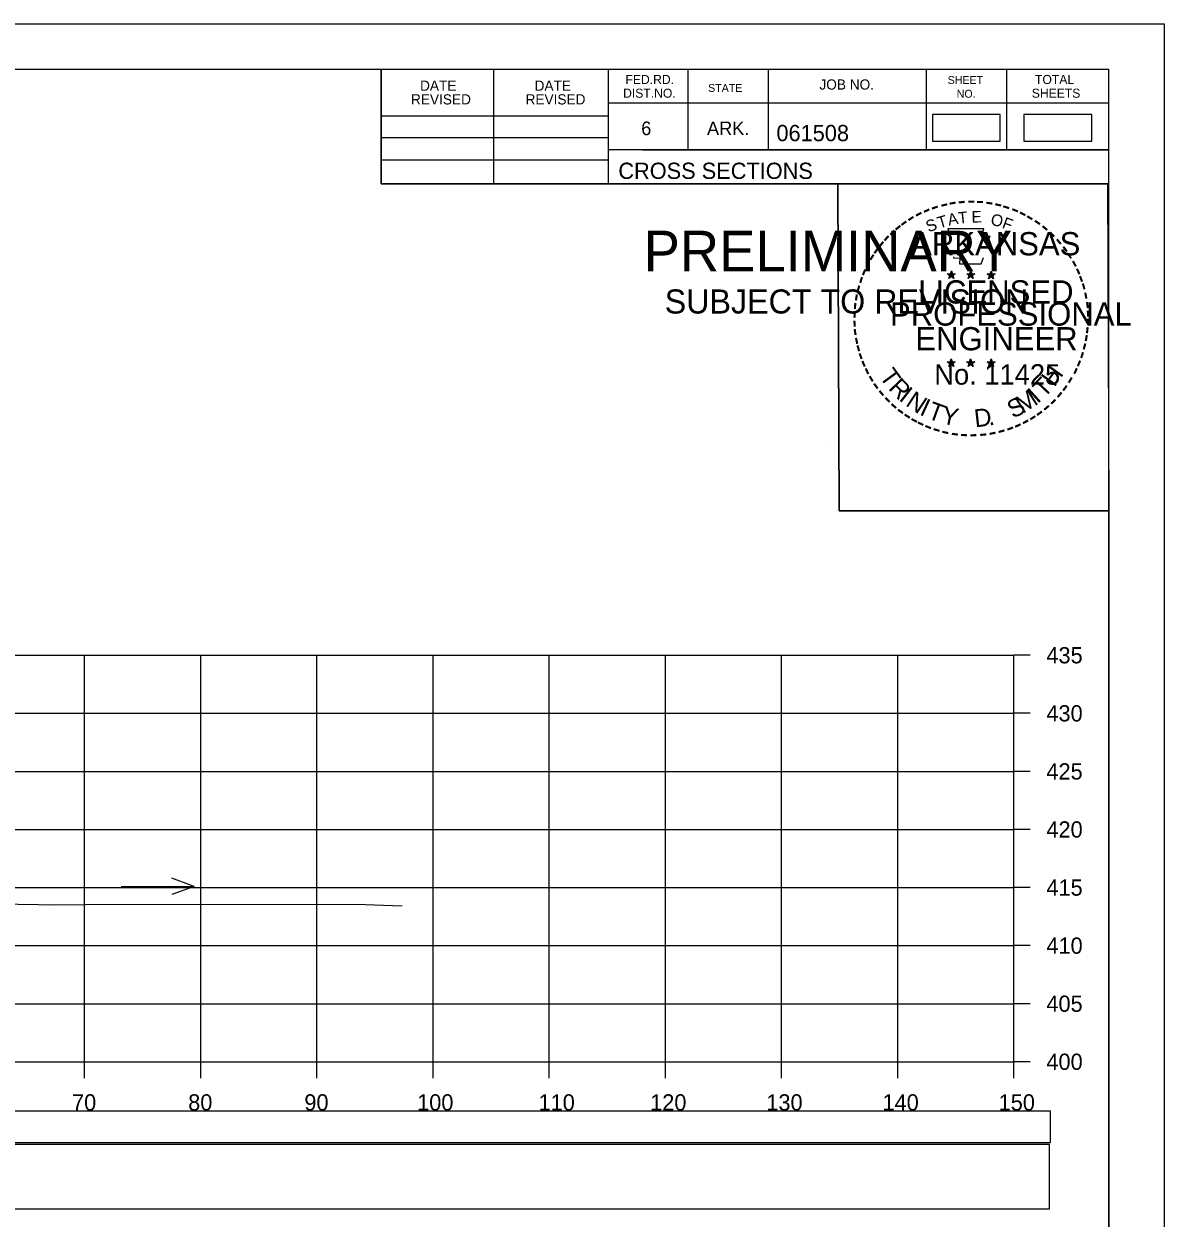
# Model space of a CAD drawing. Extents: x 1371057 to 1372761, y 380005 to 390517.
# Drawn here: x 1371625.6 to 1371723.8, y 386089.1 to 386191.9 of the extents above; entities that cross this region are included whole.
import ezdxf

# ---------------------------------------------------------------- set-up
doc = ezdxf.new("R2010")
doc.units = 0
for name, color, linetype in [('R_Axis', 7, 'Continuous'), ('R_Axis Annot', 7, 'Continuous'), ('R_Border', 7, 'Continuous'), ('R_Border PE', 7, 'Continuous'), ('R_Border Prem', 7, 'Continuous'), ('R_Detour', 7, 'Continuous'), ('R_Dimension', 7, 'Continuous'), ('R_Draft', 7, 'Continuous'), ('R_Exist Surface', 7, 'Continuous'), ('R_Grid', 7, 'Continuous'), ('R_No Plot', 7, 'Continuous'), ('R_Water Annot', 7, 'Continuous')]:
    doc.layers.add(name, color=color, linetype=linetype)

msp = doc.modelspace()

# ---------------------------------------------------------------- linework, layer by layer
at = {"layer": 'R_Axis'}
for p, q in [((1371710.87, 386102.52), (1371710.87, 386137.52)), ((1371712.27, 386137.52), (1371710.87, 386137.52)), ((1371712.27, 386132.52), (1371710.87, 386132.52)), ((1371712.27, 386127.52), (1371710.87, 386127.52)), ((1371712.27, 386122.52), (1371710.87, 386122.52)), ((1371712.27, 386117.52), (1371710.87, 386117.52)), ((1371712.27, 386112.52), (1371710.87, 386112.52)), ((1371712.27, 386107.52), (1371710.87, 386107.52)), ((1371410.87, 386102.52), (1371710.87, 386102.52)), ((1371630.87, 386101.12), (1371630.87, 386102.52)), ((1371640.87, 386101.12), (1371640.87, 386102.52)), ((1371650.87, 386101.12), (1371650.87, 386102.52)), ((1371660.87, 386101.12), (1371660.87, 386102.52)), ((1371670.87, 386101.12), (1371670.87, 386102.52)), ((1371680.87, 386101.12), (1371680.87, 386102.52)), ((1371690.87, 386101.12), (1371690.87, 386102.52)), ((1371700.87, 386101.12), (1371700.87, 386102.52)), ((1371710.87, 386101.12), (1371710.87, 386102.52)), ((1371712.27, 386102.52), (1371710.87, 386102.52))]:
    msp.add_line(p, q, dxfattribs=at)
at = {"layer": 'R_Border'}
for p, q in [((1371402.87, 386187.98), (1371719.05, 386187.98)), ((1371656.41, 386178.1), (1371656.41, 386187.98)), ((1371666.09, 386178.1), (1371666.09, 386187.98)), ((1371675.95, 386187.98), (1371675.95, 386178.1)), ((1371682.79, 386187.98), (1371682.79, 386181.04)), ((1371689.73, 386187.98), (1371689.73, 386181.04)), ((1371703.31, 386187.98), (1371703.31, 386181.04)), ((1371710.25, 386187.98), (1371710.25, 386181.04)), ((1371719.05, 385982.52), (1371719.05, 386187.98)), ((1371719.05, 386185.04), (1371675.95, 386185.04)), ((1371719.05, 386185.06), (1371719.05, 386185.06)), ((1371656.41, 386183.96), (1371675.95, 386183.96)), ((1371656.41, 386182.1), (1371675.95, 386182.1)), ((1371719.05, 386181.04), (1371675.95, 386181.04)), ((1371678.91, 386181.04), (1371719.05, 386181.04)), ((1371656.41, 386180.16), (1371675.95, 386180.16)), ((1371719.05, 386178.1), (1371656.41, 386178.1))]:
    msp.add_line(p, q, dxfattribs=at)
at = {"layer": 'R_Border PE'}
for p, q in [((1371705.14, 386170.36), (1371705.49, 386170.25)), ((1371705.14, 386170.36), (1371705.39, 386170.31)), ((1371705.14, 386170.36), (1371705.37, 386170.24)), ((1371705.49, 386170.61), (1371705.45, 386170.36)), ((1371705.49, 386170.25), (1371705.49, 386170.61)), ((1371705.49, 386170.61), (1371705.54, 386170.36)), ((1371705.83, 386170.36), (1371705.49, 386170.25)), ((1371705.83, 386170.36), (1371705.55, 386170.31)), ((1371705.83, 386170.36), (1371705.63, 386170.26)), ((1371706.81, 386170.36), (1371707.16, 386170.25)), ((1371706.81, 386170.36), (1371707.06, 386170.31)), ((1371706.81, 386170.36), (1371707.04, 386170.24)), ((1371707.16, 386170.61), (1371707.12, 386170.36)), ((1371707.16, 386170.25), (1371707.16, 386170.61)), ((1371707.16, 386170.61), (1371707.21, 386170.36)), ((1371707.5, 386170.36), (1371707.16, 386170.25)), ((1371707.5, 386170.36), (1371707.22, 386170.31)), ((1371707.5, 386170.36), (1371707.3, 386170.26)), ((1371708.57, 386170.35), (1371708.92, 386170.24)), ((1371708.57, 386170.35), (1371708.82, 386170.3)), ((1371708.57, 386170.35), (1371708.81, 386170.22)), ((1371708.92, 386170.6), (1371708.88, 386170.35)), ((1371708.92, 386170.24), (1371708.92, 386170.6)), ((1371708.92, 386170.6), (1371708.97, 386170.35)), ((1371709.27, 386170.35), (1371708.92, 386170.24)), ((1371709.27, 386170.35), (1371708.98, 386170.3)), ((1371709.27, 386170.35), (1371709.06, 386170.24)), ((1371705.27, 386169.95), (1371705.49, 386170.25)), ((1371705.27, 386169.95), (1371705.4, 386170.19)), ((1371705.27, 386169.95), (1371705.48, 386170.17)), ((1371705.7, 386169.95), (1371705.48, 386170.16)), ((1371705.7, 386169.95), (1371705.49, 386170.25)), ((1371705.7, 386169.95), (1371705.56, 386170.24)), ((1371706.94, 386169.95), (1371707.16, 386170.25)), ((1371706.94, 386169.95), (1371707.07, 386170.19)), ((1371706.94, 386169.95), (1371707.15, 386170.17)), ((1371707.37, 386169.95), (1371707.15, 386170.16)), ((1371707.37, 386169.95), (1371707.16, 386170.25)), ((1371707.37, 386169.95), (1371707.23, 386170.24)), ((1371708.7, 386169.94), (1371708.92, 386170.24)), ((1371708.7, 386169.94), (1371708.83, 386170.18)), ((1371708.7, 386169.94), (1371708.92, 386170.16)), ((1371709.13, 386169.94), (1371708.92, 386170.24)), ((1371709.13, 386169.94), (1371708.92, 386170.15)), ((1371709.13, 386169.94), (1371709, 386170.23)), ((1371705.13, 386162.79), (1371705.48, 386162.67)), ((1371705.13, 386162.79), (1371705.39, 386162.74)), ((1371705.13, 386162.79), (1371705.37, 386162.66)), ((1371705.27, 386162.38), (1371705.48, 386162.67)), ((1371705.27, 386162.38), (1371705.39, 386162.62)), ((1371705.27, 386162.38), (1371705.48, 386162.59)), ((1371705.48, 386163.04), (1371705.44, 386162.79)), ((1371705.48, 386162.67), (1371705.48, 386163.04)), ((1371705.48, 386163.04), (1371705.53, 386162.79)), ((1371705.83, 386162.79), (1371705.48, 386162.67)), ((1371705.7, 386162.38), (1371705.48, 386162.67)), ((1371705.7, 386162.38), (1371705.48, 386162.59)), ((1371705.83, 386162.79), (1371705.54, 386162.74)), ((1371705.7, 386162.38), (1371705.56, 386162.67)), ((1371705.83, 386162.79), (1371705.63, 386162.68)), ((1371706.8, 386162.79), (1371707.15, 386162.67)), ((1371706.8, 386162.79), (1371707.06, 386162.74)), ((1371706.8, 386162.79), (1371707.04, 386162.66)), ((1371706.94, 386162.38), (1371707.15, 386162.67)), ((1371706.94, 386162.38), (1371707.06, 386162.62)), ((1371706.94, 386162.38), (1371707.15, 386162.59)), ((1371707.15, 386163.04), (1371707.11, 386162.79)), ((1371707.15, 386162.67), (1371707.15, 386163.04)), ((1371707.15, 386163.04), (1371707.2, 386162.79)), ((1371707.5, 386162.79), (1371707.15, 386162.67)), ((1371707.36, 386162.38), (1371707.15, 386162.67)), ((1371707.36, 386162.38), (1371707.15, 386162.59)), ((1371707.5, 386162.79), (1371707.21, 386162.74)), ((1371707.36, 386162.38), (1371707.23, 386162.67)), ((1371707.5, 386162.79), (1371707.29, 386162.68)), ((1371708.57, 386162.78), (1371708.92, 386162.66)), ((1371708.57, 386162.78), (1371708.82, 386162.73)), ((1371708.57, 386162.78), (1371708.81, 386162.65)), ((1371708.7, 386162.37), (1371708.92, 386162.66)), ((1371708.7, 386162.37), (1371708.83, 386162.61)), ((1371708.7, 386162.37), (1371708.92, 386162.58)), ((1371708.92, 386163.03), (1371708.88, 386162.78)), ((1371708.92, 386162.66), (1371708.92, 386163.03)), ((1371708.92, 386163.03), (1371708.97, 386162.78)), ((1371709.27, 386162.78), (1371708.92, 386162.66)), ((1371709.13, 386162.37), (1371708.92, 386162.66)), ((1371709.13, 386162.37), (1371708.92, 386162.58)), ((1371709.27, 386162.78), (1371708.98, 386162.73)), ((1371709.13, 386162.37), (1371708.99, 386162.66)), ((1371709.27, 386162.78), (1371709.06, 386162.67))]:
    msp.add_line(p, q, dxfattribs=at)
for points in [[(1371705.18, 386174.24), (1371705.45, 386173.41)], [(1371708.69, 386173.31), (1371708.83, 386173.6), (1371708.15, 386173.57), (1371708.29, 386174.24), (1371705.18, 386174.24)], [(1371705.67, 386171.81), (1371705.67, 386171.73), (1371706.23, 386171.71), (1371706.18, 386171.23), (1371708.05, 386171.23), (1371708.25, 386171.77)], [(1371705.49, 386170.61), (1371705.7, 386169.95), (1371705.14, 386170.36), (1371705.83, 386170.36), (1371705.27, 386169.95), (1371705.49, 386170.61)], [(1371707.16, 386170.61), (1371707.37, 386169.95), (1371706.81, 386170.36), (1371707.5, 386170.36), (1371706.94, 386169.95), (1371707.16, 386170.61)], [(1371708.92, 386170.6), (1371709.13, 386169.94), (1371708.57, 386170.35), (1371709.27, 386170.35), (1371708.7, 386169.94), (1371708.92, 386170.6)], [(1371705.48, 386163.04), (1371705.7, 386162.38), (1371705.13, 386162.79), (1371705.83, 386162.79), (1371705.27, 386162.38), (1371705.48, 386163.04)], [(1371707.15, 386163.04), (1371707.36, 386162.38), (1371706.8, 386162.79), (1371707.5, 386162.79), (1371706.94, 386162.38), (1371707.15, 386163.04)], [(1371708.92, 386163.03), (1371709.13, 386162.37), (1371708.57, 386162.78), (1371709.27, 386162.78), (1371708.7, 386162.37), (1371708.92, 386163.03)]]:
    msp.add_lwpolyline(points, dxfattribs=at)
for centre, radius in [((1371705.49, 386170.25), 0.172), ((1371705.49, 386170.25), 0.145), ((1371705.49, 386170.25), 0.116), ((1371705.49, 386170.25), 0.0991), ((1371705.49, 386170.25), 0.0747), ((1371707.16, 386170.25), 0.172), ((1371707.16, 386170.25), 0.145), ((1371707.16, 386170.25), 0.116), ((1371707.16, 386170.25), 0.0991), ((1371707.16, 386170.25), 0.0747), ((1371708.92, 386170.23), 0.172), ((1371708.92, 386170.23), 0.145), ((1371708.92, 386170.23), 0.116), ((1371708.92, 386170.23), 0.0991), ((1371705.49, 386170.25), 0.0495), ((1371705.49, 386170.25), 0.0296), ((1371707.16, 386170.25), 0.0495), ((1371707.16, 386170.25), 0.0296), ((1371708.92, 386170.23), 0.0747), ((1371708.92, 386170.23), 0.0495), ((1371708.92, 386170.23), 0.0296), ((1371705.48, 386162.67), 0.172), ((1371705.48, 386162.67), 0.145), ((1371705.48, 386162.67), 0.116), ((1371705.48, 386162.67), 0.0991), ((1371705.48, 386162.67), 0.0747), ((1371705.48, 386162.67), 0.0495), ((1371705.48, 386162.67), 0.0296), ((1371707.15, 386162.67), 0.172), ((1371707.15, 386162.67), 0.145), ((1371707.15, 386162.67), 0.116), ((1371707.15, 386162.67), 0.0991), ((1371707.15, 386162.67), 0.0747), ((1371707.15, 386162.67), 0.0495), ((1371707.15, 386162.67), 0.0296), ((1371708.92, 386162.66), 0.172), ((1371708.92, 386162.66), 0.145), ((1371708.92, 386162.66), 0.116), ((1371708.92, 386162.66), 0.0991), ((1371708.92, 386162.66), 0.0747), ((1371708.92, 386162.66), 0.0495), ((1371708.92, 386162.66), 0.0296)]:
    msp.add_circle(centre, radius, dxfattribs=at)
at = {"layer": 'R_Detour'}
msp.add_lwpolyline([(1371407.72, 386095.57), (1371714.03, 386095.57), (1371714.03, 386098.28), (1371407.72, 386098.28)], close=True, dxfattribs=at)
at = {"layer": 'R_Dimension'}
for points in [[(1371703.87, 386181.77), (1371709.7, 386181.77), (1371709.7, 386184.08), (1371703.87, 386184.08)], [(1371711.74, 386181.77), (1371717.57, 386181.77), (1371717.57, 386184.08), (1371711.74, 386184.08)]]:
    msp.add_lwpolyline(points, close=True, dxfattribs=at)
at = {"layer": 'R_Draft'}
msp.add_lwpolyline([(1371407.64, 386089.87), (1371713.95, 386089.87), (1371713.95, 386095.4), (1371407.64, 386095.4)], close=True, dxfattribs=at)
at = {"layer": 'R_Exist Surface'}
msp.add_lwpolyline([(1371609.43, 386116.34), (1371626.89, 386116.05), (1371627.85, 386116.04), (1371630.95, 386116.05), (1371651.05, 386116.1), (1371655.04, 386116.07), (1371657.37, 386115.98), (1371658.2, 386115.95)], dxfattribs=at)
at = {"layer": 'R_Grid'}
for p, q in [((1371410.87, 386137.52), (1371710.87, 386137.52)), ((1371630.87, 386102.52), (1371630.87, 386137.52)), ((1371640.87, 386102.52), (1371640.87, 386137.52)), ((1371650.87, 386102.52), (1371650.87, 386137.52)), ((1371660.87, 386102.52), (1371660.87, 386137.52)), ((1371670.87, 386102.52), (1371670.87, 386137.52)), ((1371680.87, 386102.52), (1371680.87, 386137.52)), ((1371690.87, 386102.52), (1371690.87, 386137.52)), ((1371700.87, 386102.52), (1371700.87, 386137.52)), ((1371710.87, 386102.52), (1371710.87, 386137.52)), ((1371410.87, 386132.52), (1371710.87, 386132.52)), ((1371410.87, 386127.52), (1371710.87, 386127.52)), ((1371410.87, 386122.52), (1371710.87, 386122.52)), ((1371410.87, 386117.52), (1371710.87, 386117.52)), ((1371410.87, 386112.52), (1371710.87, 386112.52)), ((1371410.87, 386107.52), (1371710.87, 386107.52)), ((1371410.87, 386102.52), (1371710.87, 386102.52))]:
    msp.add_line(p, q, dxfattribs=at)
at = {"layer": 'R_No Plot'}
for p, q in [((1371390.47, 386191.88), (1371723.8, 386191.88)), ((1371695.09, 386155.65), (1371695.09, 386155.65))]:
    msp.add_line(p, q, dxfattribs=at)
for points in [[(1371390.46, 386191.88), (1371723.8, 386191.88), (1371723.8, 385978.54), (1371390.46, 385978.54)], [(1371636.79, 386187.98), (1371656.41, 386187.98), (1371656.41, 386178.1), (1371672.52, 386178.1), (1371695.72, 386178.1), (1371695.84, 386149.95), (1371719.05, 386149.95), (1371719.05, 385982.52), (1371402.87, 385982.52), (1371402.87, 386187.98)], [(1371695.72, 386178.1), (1371718.93, 386178.1), (1371719.05, 386149.95), (1371695.84, 386149.95)]]:
    msp.add_lwpolyline(points, close=True, dxfattribs=at)
at = {"layer": 'R_Water Annot'}
for p, q in [((1371640.3, 386117.62), (1371638.38, 386118.32)), ((1371634.02, 386117.62), (1371640.3, 386117.62)), ((1371640.3, 386117.62), (1371638.38, 386116.92))]:
    msp.add_line(p, q, dxfattribs=at)

# ---------------------------------------------------------------- texts
at = {"layer": 'R_Axis Annot'}
for s, p in [('435', (1371713.67, 386136.82)), ('430', (1371713.67, 386131.82)), ('425', (1371713.67, 386126.82)), ('420', (1371713.67, 386121.82)), ('415', (1371713.67, 386116.82)), ('410', (1371713.67, 386111.82)), ('405', (1371713.67, 386106.82)), ('400', (1371713.67, 386101.82)), ('70', (1371629.79, 386098.32)), ('80', (1371639.79, 386098.32)), ('90', (1371649.79, 386098.32)), ('100', (1371659.5, 386098.32)), ('110', (1371669.95, 386098.32)), ('120', (1371679.56, 386098.32)), ('130', (1371689.56, 386098.32)), ('140', (1371699.56, 386098.32)), ('150', (1371709.56, 386098.32))]:
    msp.add_text(s, height=1.4, dxfattribs=at).set_placement(p)
at = {"layer": 'R_Border'}
for s, height, p in [('DATE', 0.879, (1371659.75, 386186.12)), ('DATE', 0.879, (1371669.61, 386186.12)), ('FED.RD.', 0.782, (1371677.43, 386186.7)), ('JOB NO.', 0.879, (1371694.13, 386186.22)), ('SHEET', 0.684, (1371705.17, 386186.7)), ('TOTAL', 0.782, (1371712.69, 386186.7)), ('REVISED', 0.879, (1371658.97, 386184.94)), ('REVISED', 0.879, (1371668.83, 386184.94)), ('DIST.NO.', 0.782, (1371677.23, 386185.52)), ('STATE', 0.684, (1371684.55, 386186.02)), ('NO.', 0.684, (1371705.95, 386185.52)), ('SHEETS', 0.782, (1371712.41, 386185.52)), ('6', 1.17, (1371678.79, 386182.3)), ('ARK.', 1.172, (1371684.45, 386182.3)), ('061508', 1.4, (1371690.43, 386181.78)), ('CROSS SECTIONS', 1.4, (1371676.82, 386178.53))]:
    msp.add_text(s, height=height, rotation=360, dxfattribs=at).set_placement(p)
at = {"layer": 'R_Border PE'}
for s, height, rotation, p in [('-', 1.6, 10.2193, (1371705.35, 386175.77)), ('-', 1.6, 5.8968, (1371706.08, 386175.88)), ('-', 1.6, 0.1862, (1371706.86, 386175.95)), ('-', 1.6, 357.743, (1371707.58, 386175.94)), ('-', 1.6, 352.1617, (1371708.32, 386175.88)), ('-', 1.6, 28.7918, (1371702.66, 386174.78)), ('-', 1.6, 24.3072, (1371703.29, 386175.09)), ('-', 1.6, 19.1761, (1371703.93, 386175.36)), ('-', 1.6, 13.6301, (1371704.68, 386175.6)), ('A', 1, 11.2132, (1371705.27, 386174.5)), ('T', 1, 6.0228, (1371706.12, 386174.66)), ('E', 1, 0.8323, (1371707.23, 386174.77)), ('O', 1, 350.4515, (1371708.83, 386174.56)), ('-', 1.6, 347.2049, (1371709.04, 386175.77)), ('-', 1.6, 342.3362, (1371709.68, 386175.61)), ('-', 1.6, 337.8551, (1371710.41, 386175.39)), ('-', 1.6, 334.1211, (1371711.04, 386175.12)), ('-', 1.6, 38.9507, (1371701.01, 386173.63)), ('-', 1.6, 36.2317, (1371701.48, 386174.01)), ('-', 1.6, 34.0636, (1371702.06, 386174.41)), ('S', 1, 21.594, (1371703.53, 386173.91)), ('T', 1, 16.4036, (1371704.45, 386174.25)), ('F', 1, 340.0707, (1371709.79, 386174.33)), ('-', 1.6, 329.6409, (1371711.62, 386174.83)), ('-', 1.6, 325.8627, (1371712.26, 386174.47)), ('-', 1.6, 320.5297, (1371712.87, 386174.05)), ('-', 1.6, 48.423, (1371700.13, 386172.74)), ('-', 1.6, 42.9622, (1371700.58, 386173.22)), ('ARKANSAS', 2, 360, (1371702.03, 386171.95)), ('-', 1.6, 315.5786, (1371713.47, 386173.56)), ('-', 1.6, 54.2325, (1371699.31, 386171.69)), ('-', 1.6, 50.6142, (1371699.72, 386172.25)), ('-', 1.6, 309.8797, (1371714.04, 386173.01)), ('-', 1.6, 306.6522, (1371714.57, 386172.41)), ('-', 1.6, 62.8713, (1371698.67, 386170.55)), ('-', 1.6, 58.0706, (1371698.99, 386171.16)), ('-', 1.4, 303.6753, (1371715.05, 386171.84)), ('-', 1.6, 299.6684, (1371715.37, 386171.23)), ('-', 1.6, 67.7743, (1371698.41, 386169.93)), ('-', 1.6, 294.6628, (1371715.7, 386170.62)), ('-', 1.6, 75.461, (1371698, 386168.59)), ('-', 1.6, 72.3945, (1371698.2, 386169.3)), ('LICENSED', 2, 360, (1371702.63, 386167.8)), ('DWB', 0.01, 360, (1371705.47, 386170.24)), ('DWB', 0.01, 360, (1371707.14, 386170.24)), ('DWB', 0.01, 360, (1371708.91, 386170.23)), ('-', 1.6, 290.5728, (1371715.95, 386170.04)), ('-', 1.6, 285.1233, (1371716.19, 386169.46)), ('-', 1.6, 81.2013, (1371697.87, 386167.88)), ('-', 1.6, 280.5493, (1371716.39, 386168.72)), ('-', 1.6, 85.1863, (1371697.79, 386167.19)), ('PROFESSIONAL', 2, 360, (1371700.21, 386165.9)), ('-', 1.6, 276.5962, (1371716.55, 386167.95)), ('-', 1.6, 94.1959, (1371697.8, 386165.76)), ('-', 1.6, 89.0622, (1371697.77, 386166.49)), ('-', 1.6, 274.3301, (1371716.61, 386167.23)), ('-', 1.6, 269.9407, (1371716.64, 386166.6)), ('-', 1.6, 98.9479, (1371697.87, 386165.09)), ('ENGINEER', 2, 360, (1371702.39, 386163.77)), ('-', 1.6, 263.5172, (1371716.62, 386165.93)), ('-', 1.6, 101.7149, (1371698.01, 386164.36)), ('-', 1.6, 105.4578, (1371698.17, 386163.77)), ('-', 1.6, 255.7626, (1371716.44, 386164.6)), ('-', 1.6, 260.9953, (1371716.55, 386165.28)), ('-', 1.6, 109.0874, (1371698.38, 386163.13)), ('-', 1.6, 252.8681, (1371716.26, 386163.88)), ('-', 1.6, 114.0643, (1371698.64, 386162.54)), ('-', 1.6, 115.7289, (1371698.94, 386161.92)), ('T', 1.54, 306.0406, (1371699.24, 386161.51)), ('No. 11425', 1.757, 360, (1371704.02, 386160.82)), ('DWB', 0.01, 360, (1371705.47, 386162.67)), ('DWB', 0.01, 360, (1371707.14, 386162.67)), ('DWB', 0.01, 360, (1371708.91, 386162.66)), ('H', 1.54, 54.6088, (1371714.36, 386160.55)), ('-', 1.6, 244.6197, (1371715.78, 386162.58)), ('-', 1.6, 247.8887, (1371716.04, 386163.21)), ('-', 1.6, 120.4471, (1371699.3, 386161.33)), ('R', 1.54, 314.005, (1371700, 386160.46)), ('T', 1.54, 46.6444, (1371713.47, 386159.61)), ('-', 1.6, 239.0712, (1371715.38, 386161.83)), ('-', 1.6, 125.8934, (1371699.7, 386160.77)), ('-', 1.6, 130.7181, (1371700.17, 386160.22)), ('I', 1.54, 321.9694, (1371700.9, 386159.53)), ('N', 1.54, 326.5002, (1371701.47, 386159.06)), ('M', 1.54, 32.6563, (1371711.63, 386158.28)), ('I', 1.54, 42.1136, (1371712.91, 386159.13)), ('-', 1.6, 231.2538, (1371714.55, 386160.61)), ('-', 1.6, 233.8452, (1371714.98, 386161.17)), ('-', 1.6, 134.2238, (1371700.68, 386159.68)), ('-', 1.6, 138.9338, (1371701.21, 386159.21)), ('I', 1.54, 335.3603, (1371702.68, 386158.27)), ('T', 1.54, 339.8912, (1371703.34, 386157.95)), ('S', 1.54, 26.9312, (1371710.79, 386157.87)), ('-', 1.6, 221.0851, (1371713.55, 386159.53)), ('-', 1.6, 225.7653, (1371714.07, 386160.04)), ('-', 1.6, 144.6463, (1371701.76, 386158.81)), ('-', 1.6, 148.0898, (1371702.32, 386158.44)), ('Y', 1.54, 347.8556, (1371704.56, 386157.5)), ('D', 1.54, 6.3969, (1371707.54, 386157.14)), ('-', 1.6, 212.2491, (1371712.47, 386158.68)), ('-', 1.6, 215.7363, (1371713, 386159.06)), ('-', 1.6, 151.5704, (1371702.9, 386158.11)), ('-', 1.6, 154.6002, (1371703.43, 386157.86)), ('-', 1.6, 158.5612, (1371704.05, 386157.61)), ('-', 1.6, 162.7983, (1371704.74, 386157.4)), ('.', 1.54, 13.7642, (1371708.74, 386157.27)), ('-', 1.6, 195.4743, (1371709.99, 386157.5)), ('-', 1.6, 200.7184, (1371710.67, 386157.74)), ('-', 1.6, 204.2516, (1371711.29, 386158.01)), ('-', 1.6, 207.3568, (1371711.91, 386158.33)), ('-', 1.6, 167.5555, (1371705.45, 386157.23)), ('-', 1.6, 173.1155, (1371706.22, 386157.12)), ('-', 1.6, 176.5183, (1371706.97, 386157.07)), ('-', 1.6, 181.5918, (1371707.72, 386157.09)), ('-', 1.6, 185.8167, (1371708.52, 386157.16)), ('-', 1.6, 191.2858, (1371709.26, 386157.3))]:
    msp.add_text(s, height=height, rotation=rotation, dxfattribs=at).set_placement(p)
at = {"layer": 'R_Border Prem'}
for s, height, p in [('PRELIMINARY', 3.5, (1371679, 386170.57)), ('DWB', 0.01, (1371679.75, 386172.42)), ('SUBJECT TO REVISION', 2.0751, (1371680.81, 386166.94))]:
    msp.add_text(s, height=height, rotation=360, dxfattribs=at).set_placement(p)

doc.saveas('drawing.dxf')
